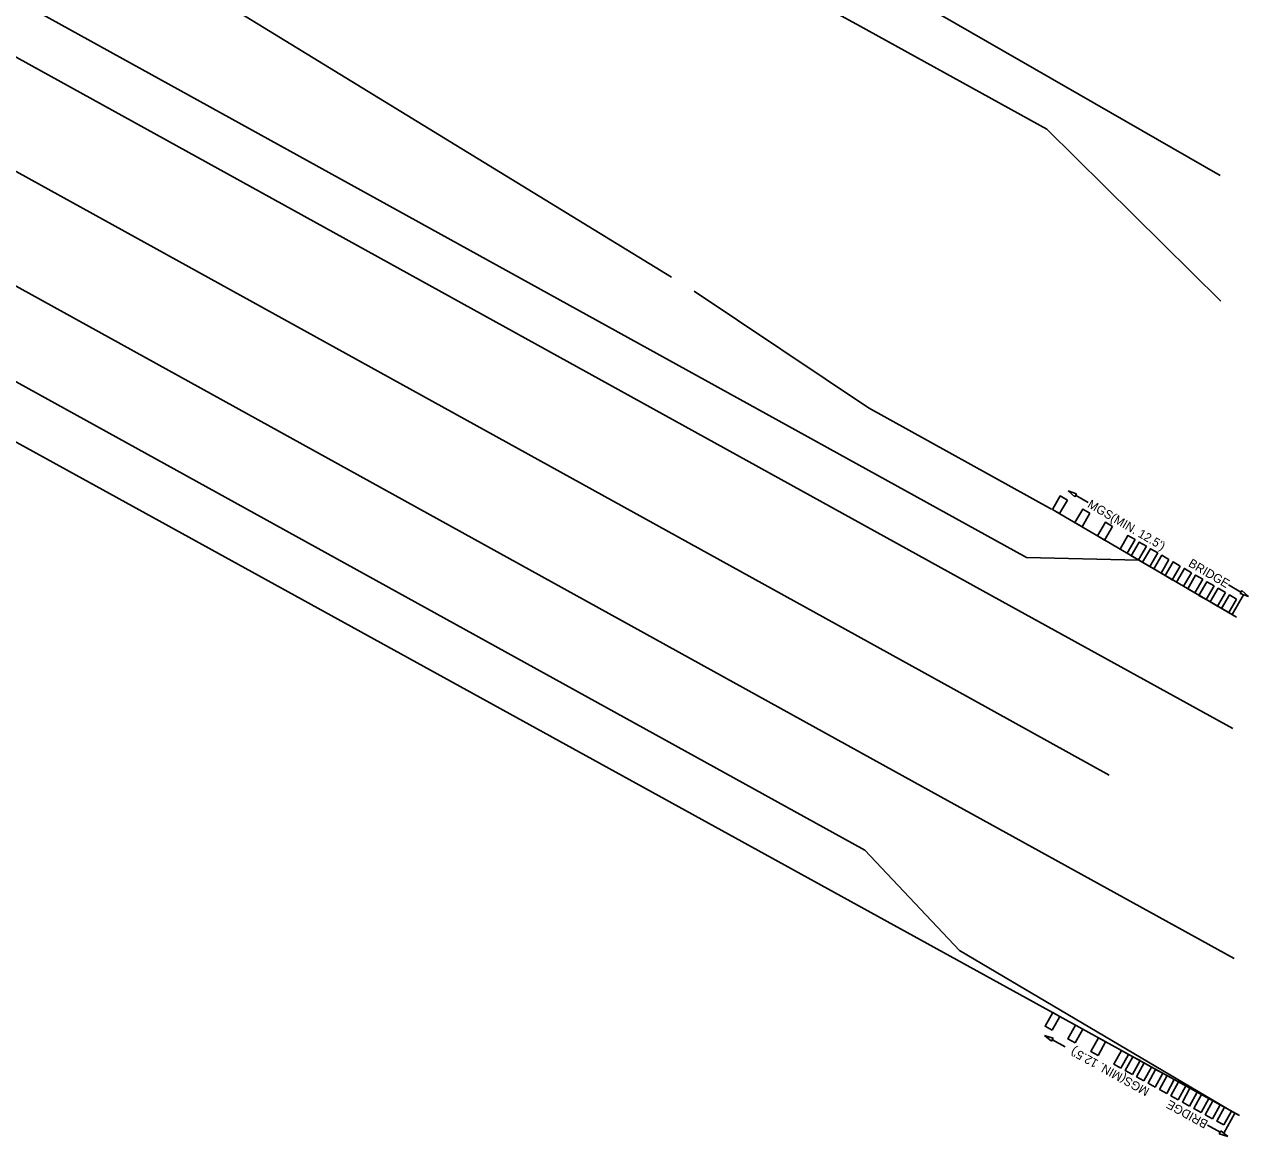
# Model space of a CAD drawing. Extents: x 76539 to 88870, y 518807 to 527554.
# Drawn here: x 88723.3 to 88869.6, y 521803.4 to 521936.4 of the extents above; entities that cross this region are included whole.
import ezdxf

# ---------------------------------------------------------------- set-up
doc = ezdxf.new("R2010")
doc.units = 0
for name, color, linetype in [('PM_P_Edge_Line', 7, 'Continuous'), ('PM_P_Lane_Line', 7, 'Continuous'), ('PV_P_Shoulder', 7, 'Continuous'), ('RD_P_GR_Lt', 7, 'Continuous'), ('RD_P_GR_Rt', 7, 'Continuous'), ('SC_Scratch13', 7, 'Continuous'), ('XS_P_Pavt_Surface', 7, 'Continuous')]:
    doc.layers.add(name, color=color, linetype=linetype)

msp = doc.modelspace()

# ---------------------------------------------------------------- linework, layer by layer
at = {"layer": 'PM_P_Edge_Line'}
for p, q in [((87716.78, 522487.5), (88840.17, 521867.4)), ((87705.15, 522466.5), (88828.57, 521846.39)), ((88825.99, 521941.45), (88866.21, 521918.33)), ((88840.17, 521867.4), (88867.72, 521852.2)), ((88828.57, 521846.39), (88867.88, 521824.69))]:
    msp.add_line(p, q, dxfattribs=at)
at = {"layer": 'PM_P_Lane_Line'}
for p, q in [((87710.96, 522477), (88834.37, 521856.9)), ((88834.37, 521856.9), (88852.96, 521846.64))]:
    msp.add_line(p, q, dxfattribs=at)
at = {"layer": 'PV_P_Shoulder'}
for p, q in [((87719.68, 522492.75), (88843.07, 521872.66)), ((87700.3, 522457.76), (88823.74, 521837.64)), ((88823.09, 521936.2), (88845.49, 521923.84)), ((88845.49, 521923.84), (88866.29, 521903.28)), ((88843.07, 521872.66), (88856.49, 521872.34)), ((88856.49, 521872.34), (88867.64, 521865.81)), ((88835.04, 521825.65), (88823.74, 521837.64)), ((88867.99, 521806.22), (88835.04, 521825.65))]:
    msp.add_line(p, q, dxfattribs=at)
at = {"layer": 'RD_P_GR_Lt'}
for p, q in [((88868.16, 521865.51), (88846.59, 521878.14)), ((88868.52, 521805.93), (88846.63, 521818.01))]:
    msp.add_line(p, q, dxfattribs=at)
for points in [[(88847.96, 521879.51), (88847.11, 521880.01), (88846.16, 521878.39), (88847.01, 521877.89)], [(88850.66, 521877.94), (88849.81, 521878.43), (88848.86, 521876.81), (88849.71, 521876.31)], [(88853.36, 521876.36), (88852.51, 521876.85), (88851.55, 521875.23), (88852.41, 521874.73)], [(88856.05, 521874.78), (88855.2, 521875.28), (88854.25, 521873.65), (88855.1, 521873.15)], [(88857.4, 521873.99), (88856.55, 521874.49), (88855.6, 521872.86), (88856.45, 521872.36)], [(88858.75, 521873.2), (88857.9, 521873.7), (88856.95, 521872.07), (88857.8, 521871.57)], [(88860.1, 521872.41), (88859.25, 521872.91), (88858.3, 521871.28), (88859.15, 521870.78)], [(88861.45, 521871.62), (88860.6, 521872.12), (88859.65, 521870.49), (88860.5, 521869.99)], [(88862.8, 521870.83), (88861.95, 521871.33), (88860.99, 521869.7), (88861.84, 521869.2)], [(88864.15, 521870.04), (88863.29, 521870.54), (88862.34, 521868.91), (88863.19, 521868.41)], [(88865.49, 521869.25), (88864.64, 521869.75), (88863.69, 521868.12), (88864.54, 521867.63)], [(88866.84, 521868.46), (88865.99, 521868.96), (88865.04, 521867.33), (88865.89, 521866.84)], [(88868.19, 521867.67), (88867.34, 521868.17), (88866.39, 521866.54), (88867.24, 521866.05)], [(88846.15, 521816.12), (88845.29, 521816.6), (88846.2, 521818.25), (88847.06, 521817.77)], [(88848.89, 521814.61), (88848.02, 521815.09), (88848.93, 521816.74), (88849.8, 521816.26)], [(88851.62, 521813.1), (88850.76, 521813.58), (88851.67, 521815.23), (88852.53, 521814.75)], [(88854.36, 521811.59), (88853.5, 521812.07), (88854.41, 521813.72), (88855.27, 521813.24)], [(88855.73, 521810.84), (88854.86, 521811.32), (88855.77, 521812.96), (88856.64, 521812.49)], [(88857.1, 521810.08), (88856.23, 521810.56), (88857.14, 521812.21), (88858.01, 521811.73)], [(88858.46, 521809.33), (88857.6, 521809.8), (88858.51, 521811.45), (88859.37, 521810.98)], [(88859.83, 521808.57), (88858.97, 521809.05), (88859.88, 521810.7), (88860.74, 521810.22)], [(88861.2, 521807.82), (88860.34, 521808.29), (88861.25, 521809.94), (88862.11, 521809.47)], [(88862.57, 521807.06), (88861.7, 521807.54), (88862.61, 521809.19), (88863.48, 521808.71)], [(88863.94, 521806.31), (88863.07, 521806.78), (88863.98, 521808.43), (88864.85, 521807.96)], [(88865.3, 521805.55), (88864.44, 521806.03), (88865.35, 521807.68), (88866.21, 521807.2)], [(88866.67, 521804.8), (88865.81, 521805.27), (88866.72, 521806.92), (88867.58, 521806.45)]]:
    msp.add_lwpolyline(points, close=True, dxfattribs=at)
at = {"layer": 'RD_P_GR_Rt'}
for p, q in [((88800.64, 521906.15), (88726.02, 521951.85)), ((88649.51, 521926.49), (88846.63, 521818.01)), ((88824.18, 521890.52), (88803.34, 521904.5)), ((88846.07, 521878.44), (88824.18, 521890.52))]:
    msp.add_line(p, q, dxfattribs=at)
at = {"layer": 'SC_Scratch13'}
for p, q in [((88849.04, 521880.27), (88848.04, 521880.61)), ((88848.04, 521880.61), (88848.83, 521879.9)), ((88848.83, 521879.9), (88849.04, 521880.27)), ((88848.94, 521880.09), (88850.43, 521879.21)), ((88868.71, 521868.51), (88867.21, 521869.39)), ((88867.64, 521865.81), (88869.02, 521868.17)), ((88868.6, 521868.33), (88868.81, 521868.69)), ((88869.61, 521867.98), (88868.6, 521868.33)), ((88868.81, 521868.69), (88869.61, 521867.98)), ((88868.16, 521865.51), (88867.64, 521865.81)), ((88846.06, 521814.81), (88845.24, 521815.5)), ((88845.24, 521815.5), (88846.26, 521815.18)), ((88846.26, 521815.18), (88846.06, 521814.81)), ((88846.16, 521814.99), (88847.68, 521814.16)), ((88867.99, 521806.22), (88866.67, 521803.83)), ((88868.52, 521805.93), (88867.99, 521806.22)), ((88866.22, 521803.92), (88864.7, 521804.76)), ((88866.32, 521804.11), (88866.12, 521803.74)), ((88867.13, 521803.42), (88866.32, 521804.11)), ((88866.12, 521803.74), (88867.13, 521803.42))]:
    msp.add_line(p, q, dxfattribs=at)
at = {"layer": 'XS_P_Pavt_Surface'}
for p, q in [((87741.96, 522532.97), (88823.09, 521936.2)), ((87719.68, 522492.75), (88843.07, 521872.66)), ((88823.74, 521837.64), (87700.3, 522457.76)), ((88823.09, 521936.2), (88845.49, 521923.84)), ((88845.49, 521923.84), (88866.29, 521903.28)), ((88843.07, 521872.66), (88856.49, 521872.34)), ((88856.49, 521872.34), (88867.64, 521865.81)), ((88867.99, 521806.22), (88867.99, 521806.22))]:
    msp.add_line(p, q, dxfattribs=at)
msp.add_lwpolyline([(88867.99, 521806.22), (88835.04, 521825.65), (88823.74, 521837.64)], dxfattribs=at)

# ---------------------------------------------------------------- texts
at = {"layer": 'SC_Scratch13'}
for s, height, rotation, p in [("MGS(MIN. 12.5')", 1.0451, 329.651, (88850.27, 521878.72)), ('BRIDGE', 1.045, 329.651, (88862.33, 521871.66)), ("MGS(MIN. 12.5')", 1.0451, 151.102, (88857.86, 521809.11)), ('BRIDGE', 1.045, 151.102, (88864.87, 521805.24))]:
    msp.add_text(s, height=height, rotation=rotation, dxfattribs=at).set_placement(p)

doc.saveas('drawing.dxf')
